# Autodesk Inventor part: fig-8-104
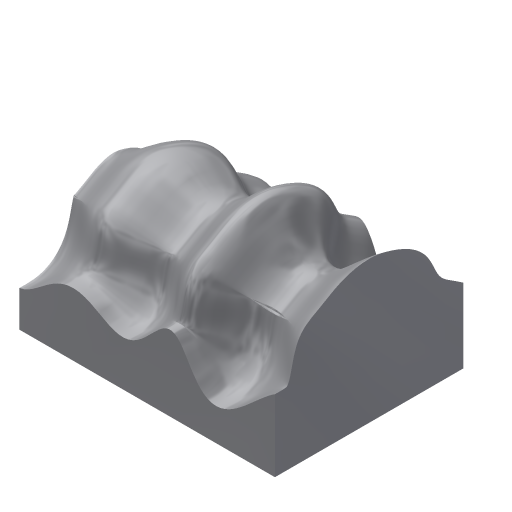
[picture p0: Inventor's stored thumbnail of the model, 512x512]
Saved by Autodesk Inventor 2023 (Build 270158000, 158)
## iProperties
Part Number: fig-8-104
Document SubType Name: Modeling
Created: 2002-12
Designer: deepak
Density: 1 g/cm^3
Material: Generic
Appearance: Aluminum - Flat
Control State: 0
Master: False
Checked Out: False
Shininess: 64.0
Length Units: 11269
Angle Units: 11279
Time Units: 11290
Mass Units: 11283
Length Display Precision: 3
Angle Display Precision: 2
Compacted: True
Density: 0.0
Volumn: 0.0
Area: 0.0
PropertySet Name: Model Information
Author: deepak
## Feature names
1. Extrusion1
## Parameters: d0 = 25 mm, d1 = 0, d2 = 0, d3 = 0
